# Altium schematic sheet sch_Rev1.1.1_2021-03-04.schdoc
size 525 x 378 mm
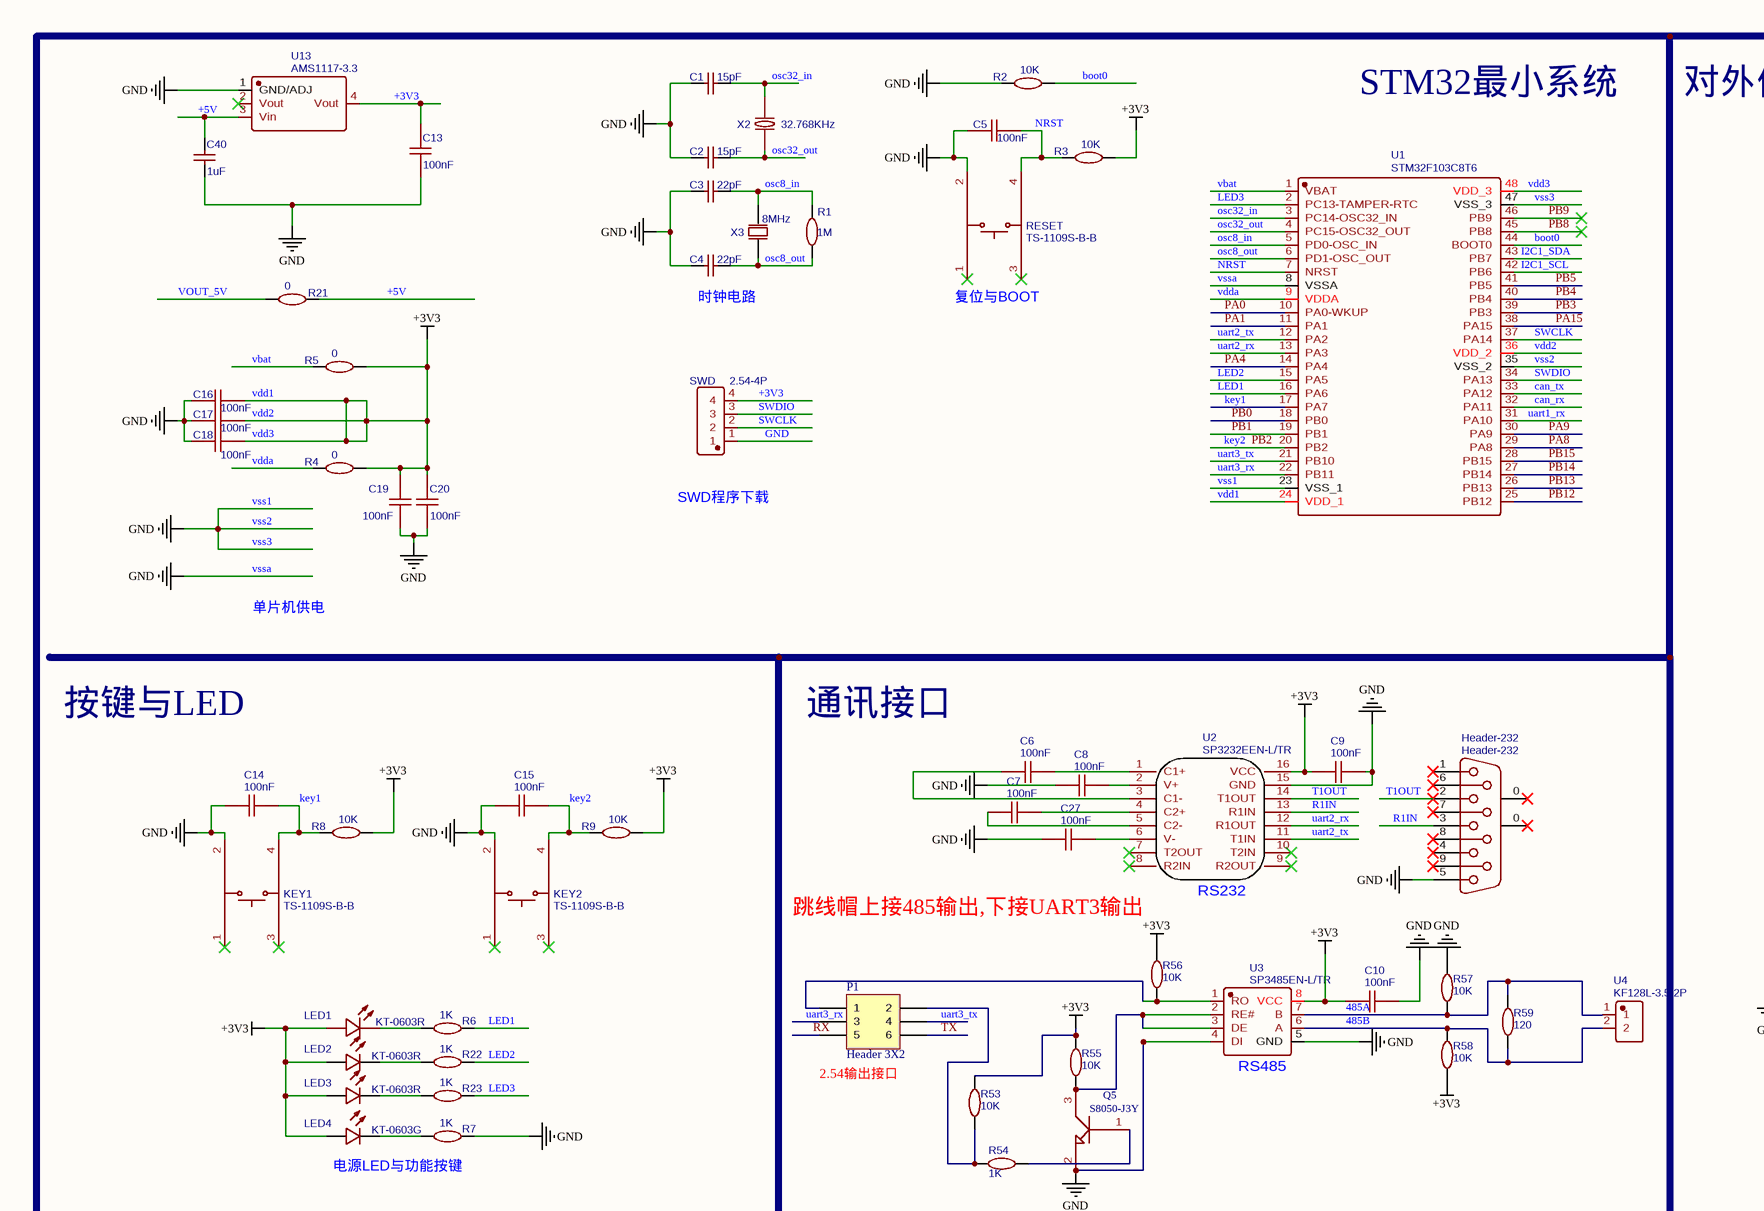
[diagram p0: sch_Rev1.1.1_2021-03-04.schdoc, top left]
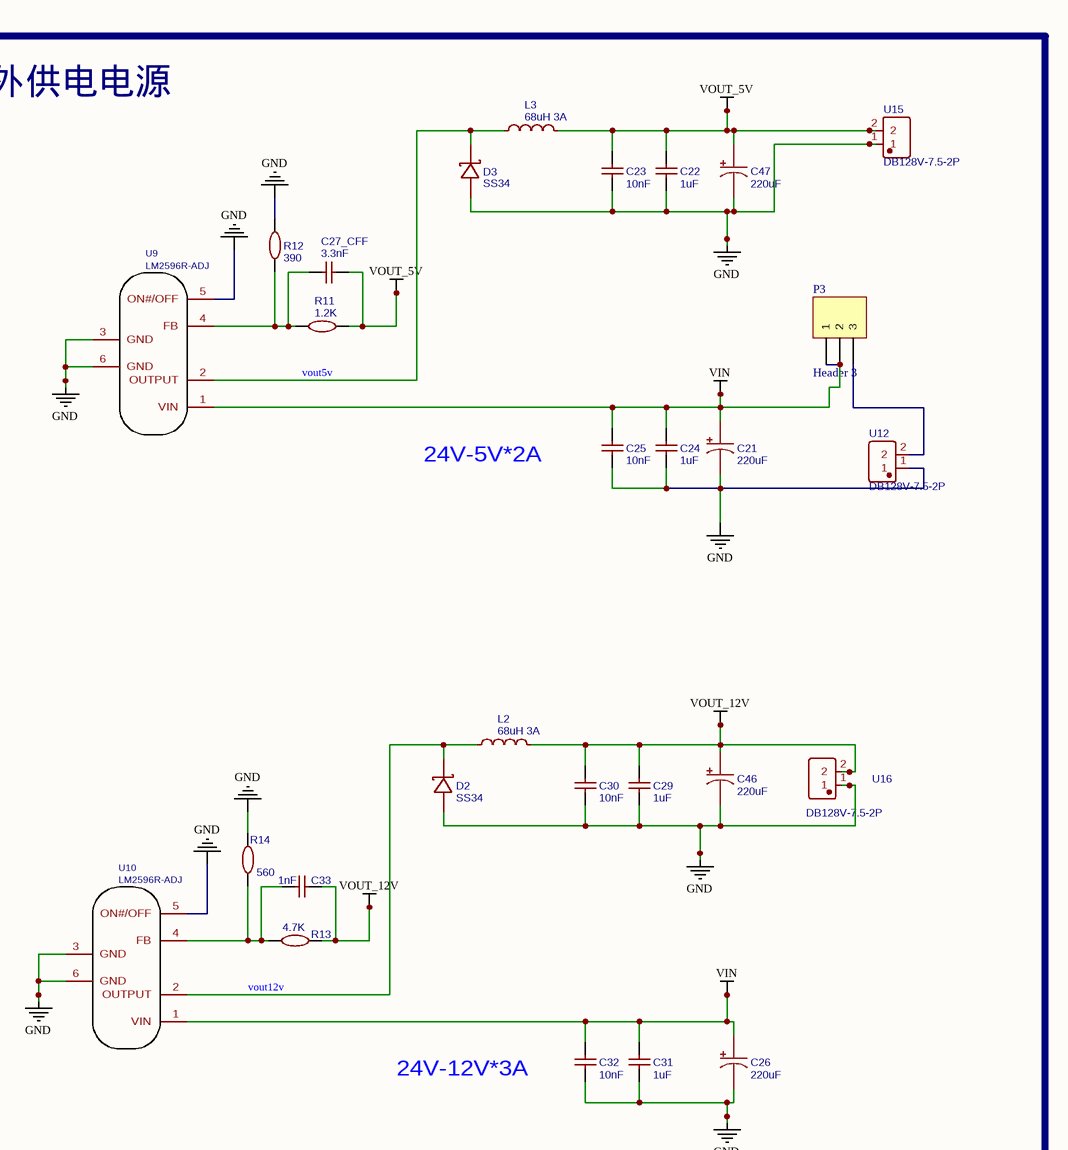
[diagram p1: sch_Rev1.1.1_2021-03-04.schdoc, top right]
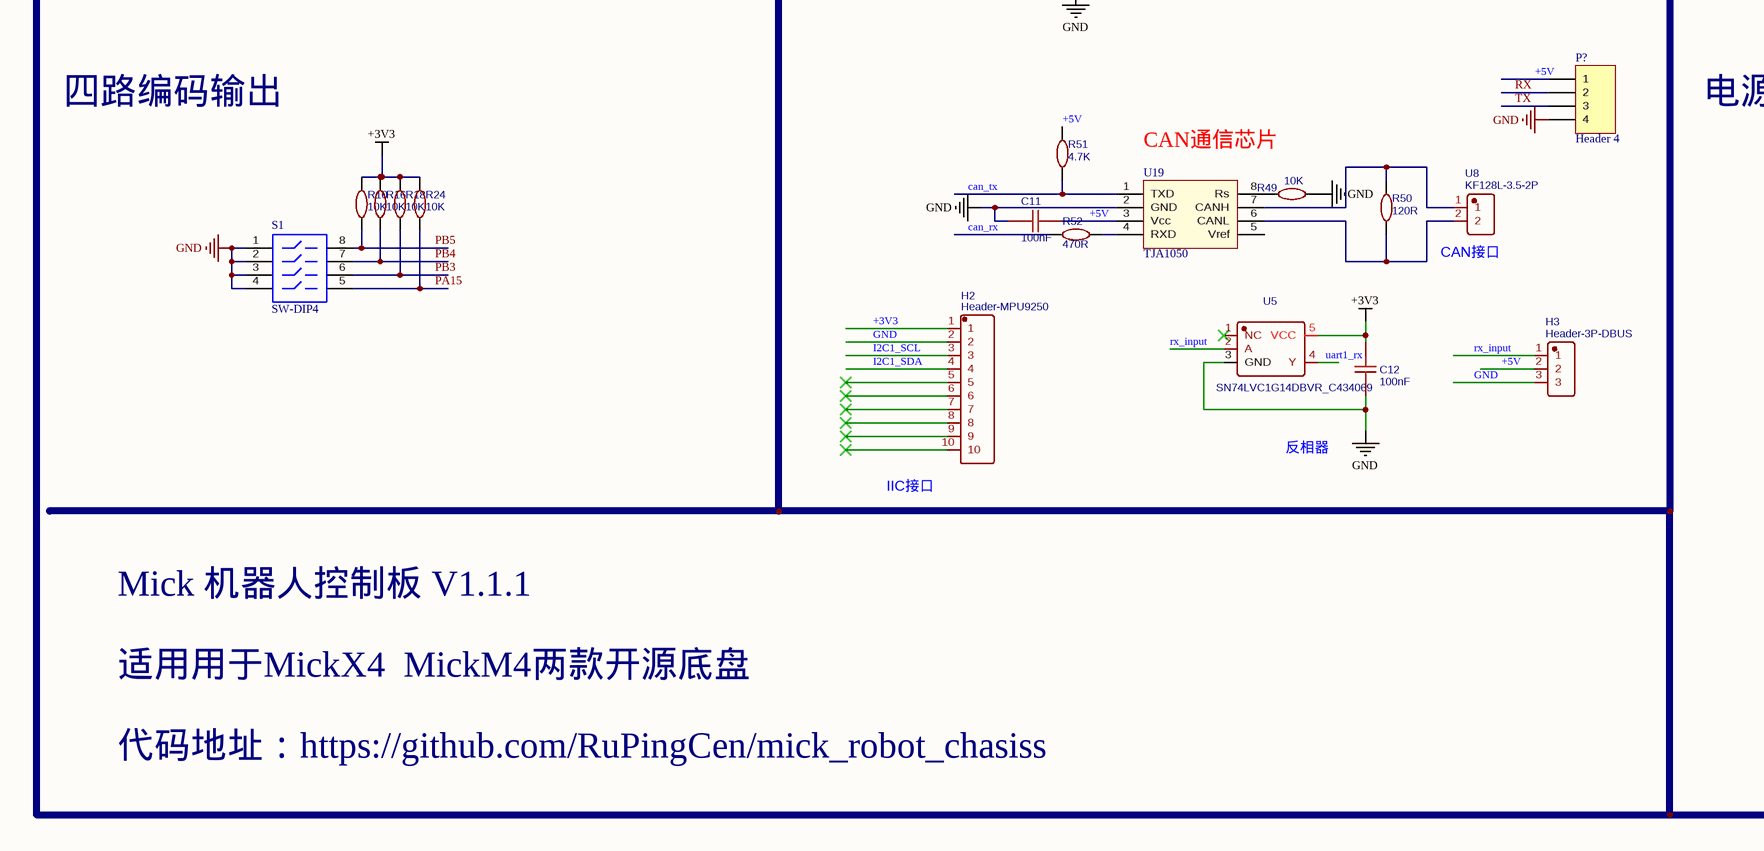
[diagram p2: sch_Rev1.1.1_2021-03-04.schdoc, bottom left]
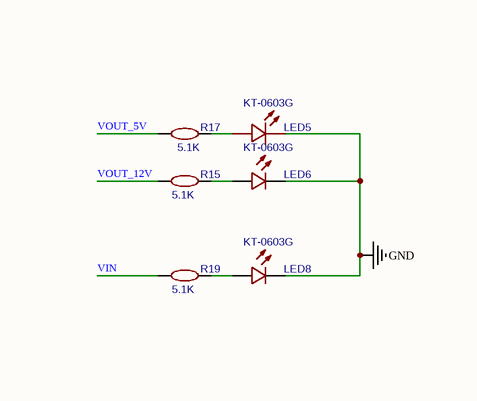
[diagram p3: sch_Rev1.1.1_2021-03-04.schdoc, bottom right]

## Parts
C1  15pF  [C0603]
C2  15pF  [C0603]
C3  22pF  [C0603]
C4  22pF  [C0603]
C5  100nF  [C0603]
C6  100nF  [C0603]
C7  100nF  [C0603]
C8  100nF  [C0603]
C9  100nF  [C0603]
C10  100nF  [C0603]
C11  100nF  [C0603]
C12  100nF  [C0603]
C13  100nF  [C0603]
C14  100nF  [C0603]
C15  100nF  [C0603]
C16  100nF  [C0603]
C17  100nF  [C0603]
C18  100nF  [C0603]
C19  100nF  [C0603]
C20  100nF  [C0603]
C21  220uF  [CAP-SMD_BD10.0-L10.3-W10.3-RD]
C22  1uF  [C0603]
C23  10nF  [C0603]
C24  1uF  [C0603]
C25  10nF  [C0603]
C26  220uF  [CAP-SMD_BD10.0-L10.3-W10.3-RD]
C27  100nF  [C0603]
C27_CFF  3.3nF  [C0603]
C29  1uF  [C0603]
C30  10nF  [C0603]
C31  1uF  [C0603]
C32  10nF  [C0603]
C33  1nF  [C0603]
C40  1uF  [C0603]
C46  220uF  [CAP-SMD_BD8.0-L8.3-W8.3-RD]
C47  220uF  [CAP-SMD_BD8.0-L8.3-W8.3-RD]
D2  SS34  [SMC_L6.9-W5.9-LS7.9-RD]
D3  SS34  [SMC_L6.9-W5.9-LS7.9-RD]
H2  Header-MPU9250  [HDR-TH_10P-P2.54-V]
H3  Header-3P-DBUS  [HDR-TH_3P-P2.54-V]
Header-232  Header-232  [DSUB-TH_9P-P2.74-S2.84_L18.5-W30.8-M]
KEY1  TS-1109S-B-B  [SW-SMD_4P-L4.5-W4.5-P3.00-LS7.0]
KEY2  TS-1109S-B-B  [SW-SMD_4P-L4.5-W4.5-P3.00-LS7.0]
L2  68uH 3A  [IND-SMD_L11.5-W10.0_104CDMCCDS]
L3  68uH 3A  [IND-SMD_L11.5-W10.0_104CDMCCDS]
LED1  KT-0603R  [LED0603-R-RD]
LED2  KT-0603R  [LED0603-R-RD]
LED3  KT-0603R  [LED0603-R-RD]
LED4  KT-0603G  [LED0603-R-RD]
LED5  KT-0603G  [LED0603-R-RD]
LED6  KT-0603G  [LED0603-R-RD]
LED8  KT-0603G  [LED0603-R-RD]
P1  Header 3X2  [HDR2X3]
P3  Header 3  [SW-3]
P?  Header 4  [HDR1X4]
Q5  S8050-J3Y  [S8050-J3Y]
R1  1M  [R0603]
R2  10K  [R0603]
R3  10K  [R0603]
R4  0  [R0603]
R5  0  [R0603]
R6  1K  [R0603]
R7  1K  [R0603]
R8  10K  [R0603]
R9  10K  [R0603]
R10  10K  [R0603]
R11  1.2K  [R0603]
R12  390  [R0603]
R13  4.7K  [R0603]
R14  560  [R0603]
R15  5.1K  [R0603]
R16  10K  [R0603]
R17  5.1K  [R0603]
R18  10K  [R0603]
R19  5.1K  [R0603]
R21  0  [R0603]
R22  1K  [R0603]
R23  1K  [R0603]
R24  10K  [R0603]
R49  10K  [R0603]
R50  120R  [R0603]
R51  4.7K  [R0603]
R52  470R  [R0603]
R53  10K  [R0603]
R54  1K  [R0603]
R55  10K  [R0603]
R56  10K  [R0603]
R57  10K  [R0603]
R58  10K  [R0603]
R59  120  [R0603]
RESET  TS-1109S-B-B  [SW-SMD_4P-L4.5-W4.5-P3.00-LS7.0]
S1  SW-DIP4  [SW-SOP-8]
SWD  2.54-4P  [HDR-TH_4P-P2.54-V]
U1  STM32F103C8T6  [LQFP-48_48P-L7.0-W7.0-P0.50-LS9.0-BL]
U2  SP3232EEN-L/TR  [SOIC-16_L9.9-W3.9-P1.27-LS6.0-BL]
U3  SP3485EN-L/TR  [SOIC-8_L5.0-W4.0-P1.27-LS6.0-BL]
U4  KF128L-3.5-2P  [CONN-TH_P3.50_KF128L-3.5-2P]
U5  SN74LVC1G14DBVR_C434069  [SOT-23-5_L3.0-W1.7-P0.95-LS2.8-BR]
U8  KF128L-3.5-2P  [CONN-TH_P3.50_KF128L-3.5-2P]
U9  LM2596R-ADJ  [TO-263-5_L10.2-W9.9-P1.70-LS14.4-TL]
U10  LM2596R-ADJ  [TO-263-5_L10.2-W9.9-P1.70-LS14.4-TL]
U12  DB128V-7.5-2P  [CONN-TH_2P-P7.50_DB128V-7.5-2P]
U13  AMS1117-3.3  [SOT-223-3_L6.5-W3.4-P2.30-LS7.0-BR]
U15  DB128V-7.5-2P  [CONN-TH_2P-P7.50_DB128V-7.5-2P]
U16  DB128V-7.5-2P  [CONN-TH_2P-P7.50_DB128V-7.5-2P]
U19  TJA1050  [SOP-8]
X2  32.768KHz  [FC-135R_L3.2-W1.5]
X3  8MHz  [OSC-SMD_L11.5-W4.8-P9.50]

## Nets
+3V3: C9.1 C10.1 C12.2 C13.2 C16.2 C17.2 C18.2 C19.2 C20.2 H2.1 LED1.1(A) LED2.1(A) LED3.1(A) LED4.1(A) R3.1 R4.2 R5.2 R8.1 R9.1 R10.2 R16.2 R18.2 R24.2 R53.1 R55.1 R56.1 R58.2 SWD.4 U1.24(VDD_1) U1.36(VDD_2) U1.48(VDD_3) U2.16(VCC) U3.8(VCC) U5.5(VCC) U13.4(Vout)  [also labelled vdd1, vdd2, vdd3]
GND: C1.1 C2.1 C3.1 C4.1 C5.1 C8.1 C9.2 C10.2 C11.2 C12.1 C13.1 C14.1 C15.1 C16.1 C17.1 C18.1 C19.1 C20.1 C21.2 C22.1 C23.1 C24.1 C25.1 C26.2 C27.1 C29.1 C30.1 C31.1 C32.1 C40.1 C46.2 C47.2 D2.2(A) D3.2(A) H2.2 H3.3 Header-232.5 KEY1.2 KEY2.2 LED5.2(K) LED6.2(C) LED8.2(C) P?.4 Q5.2(E) R2.2 R7.2 R12.2 R14.2 R49.1 R57.1 RESET.2 S1.1 S1.2 S1.3 S1.4 SWD.1 U1.8(VSSA) U1.23(VSS_1) U1.35(VSS_2) U1.47(VSS_3) U2.15(GND) U3.4(DI) U3.5(GND) U5.3(GND) U9.3(GND) U9.5(ON#/OFF) U9.6(GND) U10.3(GND) U10.5(ON#/OFF) U10.6(GND) U12.1 U13.1(GND/ADJ) U15.1 U16.1 U19.2(GND)  [also labelled vss1, vss2, vss3, vssa]
VIN: C21.1 C24.2 C25.2 C26.1 C31.2 C32.2 P3.1 P3.2 R19.1 U9.1(VIN) U10.1(VIN)
VOUT_5V: C22.2 C23.2 C27_CFF.2 C47.1 L3.2 R11.2 R17.1 R21.1 U15.2
VOUT_12V: C29.2 C30.2 C33.2 C46.1 L2.2 R13.2 R15.1 U16.2
485A: R57.2 R59.1 U3.7(B) U4.1
485B: R58.1 R59.2 U3.6(A) U4.2
+5V: C11.1 C40.2 H3.2 P?.1 R21.2 R51.1 U13.3(Vin) U19.3(Vcc)
boot0: R2.1 U1.44(BOOT0)
can_rx: R52.1 U1.32(PA11)
can_tx: R51.2 U1.33(PA12) U19.1(TXD)
I2C1_SCL: H2.3 U1.42(PB6)
I2C1_SDA: H2.4 U1.43(PB7)
key1: C14.2 KEY1.4 R8.2 U1.17(PA7)
key2: C15.2 KEY2.4 R9.2 U1.20(PB2)  [also labelled PB2]
LED1: R6.2 U1.16(PA6)
LED2: R22.2 U1.15(PA5)
LED3: R23.2 U1.2(PC13-TAMPER-RTC)
NRST: C5.2 R3.2 RESET.4 U1.7(NRST)
osc8_in: C3.2 R1.2 U1.5(PD0-OSC_IN) X3.1(OSC1)
osc8_out: C4.2 R1.1 U1.6(PD1-OSC_OUT) X3.2(OSC2)
osc32_in: C1.2 U1.3(PC14-OSC32_IN) X2.2
osc32_out: C2.2 U1.4(PC15-OSC32_OUT) X2.1
PA0: U1.10(PA0-WKUP)
PA1: U1.11(PA1)
PA4: U1.14(PA4)
PA8: U1.29(PA8)
PA9: U1.30(PA9)
PA15: R24.1 S1.5 U1.38(PA15)
PB0: U1.18(PB0)
PB1: U1.19(PB1)
PB3: R18.1 S1.6 U1.39(PB3)
PB4: R16.1 S1.7 U1.40(PB4)
PB5: R10.1 S1.8 U1.41(PB5)
PB8: U1.45(PB8)
PB9: U1.46(PB9)
PB12: U1.25(PB12)
PB13: U1.26(PB13)
PB14: U1.27(PB14)
PB15: U1.28(PB15)
R1IN: Header-232.3 U2.13(R1IN)
RX: P1.5 P?.2
rx_input: H3.1 U5.2(A)
SWCLK: SWD.2 U1.37(PA14)
SWDIO: SWD.3 U1.34(PA13)
T1OUT: Header-232.2 U2.14(T1OUT)
TX: P1.6 P?.3
uart1_rx: U1.31(PA10) U5.4(Y)
uart2_rx: U1.13(PA3) U2.12(R1OUT)
uart2_tx: U1.12(PA2) U2.11(T1IN)
uart3_rx: P1.3 U1.22(PB11)
uart3_tx: P1.4 U1.21(PB10)
vbat: R5.1 U1.1(VBAT)
vdda: R4.1 U1.9(VDDA)
vout5v: D3.1(K) L3.1 U9.2(OUTPUT)
vout12v: D2.1(K) L2.1 U10.2(OUTPUT)
NetC6_1: C6.1 U2.3(C1-)
NetC6_2: C6.2 U2.1(C1+)
NetC7_1: C7.1 U2.5(C2-)
NetC7_2: C7.2 U2.4(C2+)
NetC8_2: C8.2 U2.2(V+)
NetC27_2: C27.2 U2.6(V-)
NetC27_CFF_1: C27_CFF.1 R11.1 R12.1 U9.4(FB)
NetC33_1: C33.1 R13.1 R14.1 U10.4(FB)
NetLED1_2: LED1.2(K) R6.1
NetLED2_2: LED2.2(C) R22.1
NetLED3_2: LED3.2(C) R23.1
NetLED4_2: LED4.2(C) R7.1
NetLED5_1: LED5.1(A) R17.2
NetLED6_1: LED6.1(A) R15.2
NetLED8_1: LED8.1(A) R19.2
NetP1_1: P1.1 R56.2 U3.1(RO)
NetP1_2: P1.2 R53.2 R54.1
NetP3_3: P3.3 U12.2
NetQ5_1: Q5.1(B) R54.2
NetQ5_3: Q5.3(C) R55.2 U3.2(RE#) U3.3(DE)
NetR49_2: R49.2 U19.8(Rs)
NetR50_1: R50.1 U8.1 U19.7(CANH)
NetR50_2: R50.2 U8.2 U19.6(CANL)
NetR52_2: R52.2 U19.4(RXD)

Not connected (* = marked no-connect by the designer): H2 5* 6* 7* 8* 9* 10*; Header-232 0* 1* 4* 6* 7* 8* 9*; KEY1 1* 3*; KEY2 1* 3*; RESET 1* 3*; U2 7(T2OUT)* 8(R2IN)* 9(R2OUT)* 10(T2IN)*; U5 1(NC)*; U13 2(Vout)*; U19 5(Vref)

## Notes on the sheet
- STM32最小系统
- 对外供电电源
- (near C4) 时钟电路
- (near RESET) 复位与BOOT
- 24V-5V*2A
- (near SWD) SWD程序下载
- 单片机供电
- 按键与LED
- 通讯接口
- (near U2) RS232
- 跳线帽上接485输出,下接UART3输出
- (near P1) 2.54输出接口
- (near U3) RS485
- 24V-12V*3A
- 电源LED与功能按键
- 四路编码输出
- 电源指示灯
- (near U19) CAN通信芯片
- (near U8) CAN接口
- 反相器
- (near H2) IIC接口
- Mick 机器人控制板 V1.1.1
- 适用用于MickX4  MickM4两款开源底盘
- 代码地址：https://github.com/RuPingCen/mick_robot_chasiss

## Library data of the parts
C1 C2 = 15pF: BOM_Manufacturer Part: CL10C150JB8NNNC; BOM_Manufacturer: SAMSUNG; nameAlias: Capacitance; SMT Type: Basic
C3 C4 = 22pF: BOM_Manufacturer Part: CL10C220JB8NNNC; BOM_Manufacturer: SAMSUNG; nameAlias: Capacitance; SMT Type: Basic
C5-C20 C27 = 100nF: BOM_Manufacturer: YAGEO; BOM_Manufacturer Part: CC0603KRX7R9BB104; nameAlias: Capacitance; SMT Type: Basic
C21 C26 = 270uF: 50V; BOM_Manufacturer: Lelon; BOM_Manufacturer Part: HBW271M1VTR-1010K; nameAlias: Capacitance; Contributor: LCSC; SMT Type: Extend
C22 C24 C29 C31 = 1uF: BOM_Manufacturer Part: CL10A105KB8NNNC; BOM_Manufacturer: SAMSUNG; nameAlias: Capacitance; SMT Type: Basic
C23 C25 C30 C32 = 10nF: BOM_Manufacturer: FH; BOM_Manufacturer Part: 0603B103K500NT; nameAlias: Capacitance; SMT Type: Basic
C27_CFF = 3.3nF: BOM_Manufacturer Part: CL10B332KB8NNNC; BOM_Manufacturer: SAMSUNG; nameAlias: Capacitance; SMT Type: Basic
C33 = 1nF: BOM_Manufacturer Part: CL10B102KB8NNNC; BOM_Manufacturer: SAMSUNG; nameAlias: Capacitance; SMT Type: Basic
C40 = 470nF: BOM_Manufacturer Part: CL21B474KBFNNNE; BOM_Manufacturer: SAMSUNG; nameAlias: Capacitance; SMT Type: Basic
C46 C47 = 220uF: 25V; BOM_Manufacturer: Lelon; BOM_Manufacturer Part: VEH221M1VTR-0810; nameAlias: Capacitance; Contributor: LCSC; SMT Type: Extend
D2 D3 = B540C-13-F: BOM_Manufacturer: DIODES; SMT Type: Extend
H2 = Header-Male-2.54_1x10: BOM_Manufacturer Part: Headers  Pins2.54mm1*10P; SMT Type: Extend
H3 = Z-211-0311-0021-001: 蓝色排针; BOM_Manufacturer: ZHENGLING; Contributor: LCSC; SMT Type: Extend
Header-232 = 5747844-6: BOM_Manufacturer: TE Connectivity; Contributor: LCSC; SMT Type: Extend
KEY1 KEY2 RESET = TS-1109S-B-B: BOM_Manufacturer: XKB Enterprise; Contributor: LCSC; SMT Type: Extend
L2 = 68uH 3A: BOM_Manufacturer: YJYCOIN; BOM_Manufacturer Part: YSPI1050-680M; nameAlias: Inductance; Contributor: LCSC; SMT Type: Extend
L3 = 68uH: BOM_Manufacturer: YJYCOIN; BOM_Manufacturer Part: YSPI1050-680M; nameAlias: Inductance; Contributor: LCSC; SMT Type: Extend
LED1 = R: BOM_Manufacturer: KENTO; SMT Type: Basic
LED2 = YR: BOM_Manufacturer: EVERLIGHT; BOM_Manufacturer Part: 19-217/GHC-YR1S2/3T; SMT Type: Basic
LED3 LED4 = CY: BOM_Manufacturer: EVERLIGHT; BOM_Manufacturer Part: 19-213/Y2C-CQ2R2L/3T(CY); SMT Type: Basic
LED5 = KT-0603R: BOM_Manufacturer: KENTO; SMT Type: Basic
LED6 = 19-213/Y2C-CQ2R2L/3T(CY): BOM_Manufacturer: EVERLIGHT; SMT Type: Basic
LED8 = 19-217/GHC-YR1S2/3T: BOM_Manufacturer: EVERLIGHT; SMT Type: Basic
P1 = Header 3X2: Header, 3-Pin, Dual row 485切换 （黑）
P3 = Header 3: Header, 3-Pin 电源开关
P? = Header 4: Header, 4-Pin 串口3输出
R1 = 1M: BOM_Manufacturer: UniOhm; BOM_Manufacturer Part: 0603WAF1004T5E; nameAlias: Resistance (Ohms); SMT Type: Basic
R2 R3 R8 R9 R49-R59 = 10K: BOM_Manufacturer: UniOhm; BOM_Manufacturer Part: 0603WAF1002T5E; nameAlias: Resistance (Ohms); SMT Type: Basic
R4 R5 R21 = 0: BOM_Manufacturer: UniOhm; BOM_Manufacturer Part: 0603WAF0000T5E; nameAlias: Resistance (Ohms); SMT Type: Basic
R6 R7 R10 R16-R18 R22-R24 = 1K: BOM_Manufacturer: UniOhm; BOM_Manufacturer Part: 0603WAF1001T5E; nameAlias: Resistance (Ohms); SMT Type: Basic
R11 = 1.2K: BOM_Manufacturer: UniOhm; BOM_Manufacturer Part: 0603WAF1201T5E; nameAlias: Resistance (Ohms); SMT Type: Basic
R12 = 390: BOM_Manufacturer: UniOhm; BOM_Manufacturer Part: 0603WAF3900T5E; nameAlias: Resistance (Ohms); SMT Type: Basic
R13 = 4.7K: BOM_Manufacturer: UniOhm; BOM_Manufacturer Part: 0603WAF4701T5E; nameAlias: Resistance (Ohms); SMT Type: Basic
R14 = 560: BOM_Manufacturer: UniOhm; BOM_Manufacturer Part: 0603WAF5600T5E; nameAlias: Resistance (Ohms); SMT Type: Basic
R15 = 2.4K: BOM_Manufacturer: UniOhm; BOM_Manufacturer Part: 0603WAF2401T5E; nameAlias: Resistance (Ohms); SMT Type: Basic
R19 = 5.1K: BOM_Manufacturer Part: 0603WAF5101T5E; BOM_Manufacturer: UniOhm; nameAlias: Resistance (Ohms); SMT Type: Basic
S1 = SW-DIP4: DIP Switch 拨码开关
SWD = 2.54-4P: SWD程序下载 （黄色）; BOM_Manufacturer: ZHENGLING; BOM_Manufacturer Part: Z-211-0411-0021-001; Contributor: LCSC; SMT Type: Extend
U1 = STM32F103C8T6: BOM_Manufacturer: STMicroelectronics; SMT Type: Basic
U2 = SP3232EEN-L/TR: BOM_Manufacturer: EXAR; SMT Type: Extend
U3 = SP3485EN-L/TR: 485芯片; BOM_Manufacturer: EXAR; SMT Type: Basic
U4 U8 = KF128L-3.5-2P: 接头3.5; BOM_Manufacturer: Cixi Kefa Elec; Contributor: LCSC; SMT Type: Extend
U5 = SN74LVC1G14DBVR_C434069: 反向器; BOM_Manufacturer: Youtai Semiconductor Co., Ltd.; Contributor: LCSC; SMT Type: Extend
U9 U10 = LM2596R-ADJ: BOM_Manufacturer: TI; BOM_Manufacturer Part: LM2596SX-ADJ/NOPB; SMT Type: Extend
U12 U15 U16 = DB128V-7.5-2P: 接头7.5; BOM_Manufacturer: DIBO; Contributor: LCSC; SMT Type: Extend
U13 = AMS1117-3.3: BOM_Manufacturer: AMS; sourceId: dwIGgezVh; SMT Type: Basic
U19 = PCA82C250: CAN收发
X2 = 32.768KHz: BOM_Manufacturer Part: Q13FC1350000400; BOM_Manufacturer: EPSON; nameAlias: Frequency; SMT Type: Basic
X3 = 8MHz: BOM_Manufacturer: YXC; BOM_Manufacturer Part: X49SM8MSD2SC; nameAlias: Frequency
